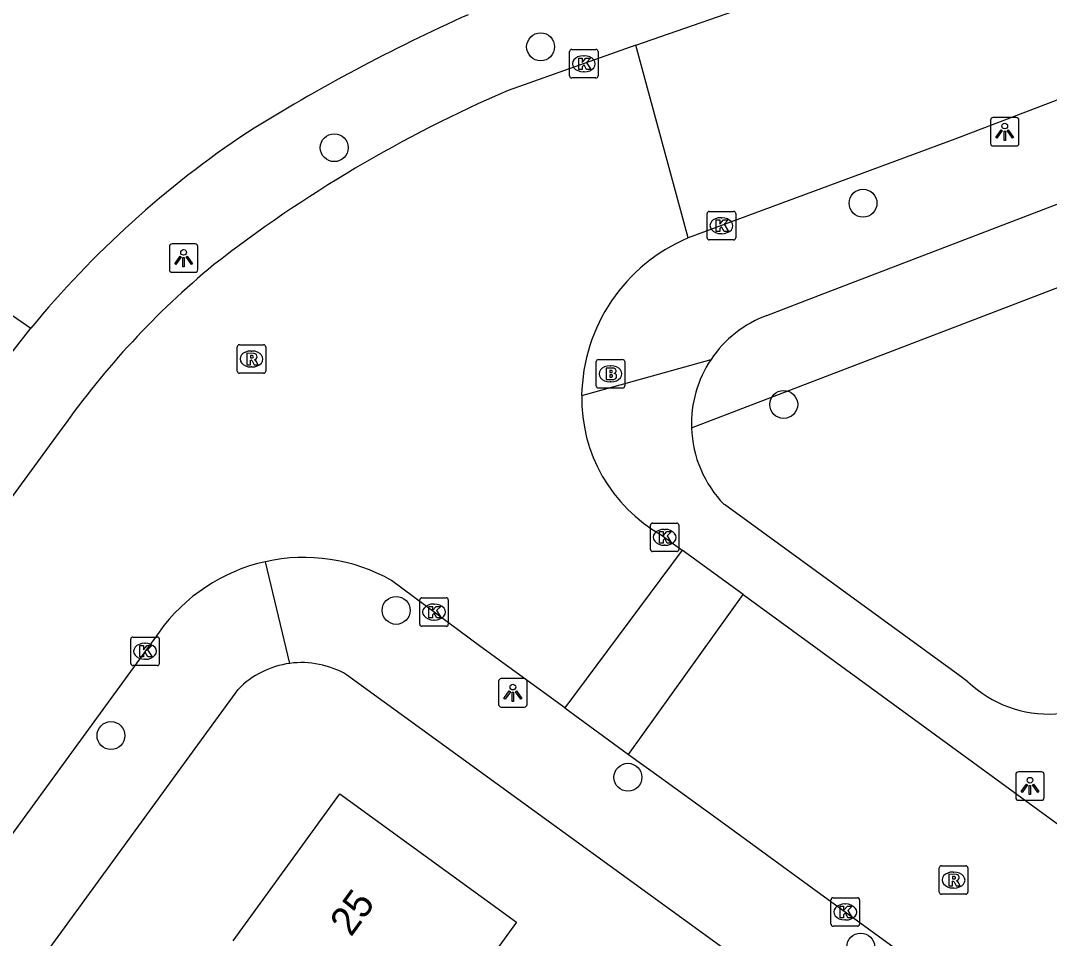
# Model space of a CAD drawing. Extents: x 159675 to 160530, y 382179 to 382901.
# Drawn here: x 160160.32 to 160196.38, y 382662.72 to 382694.9 of the extents above; entities that cross this region are included whole.
import ezdxf

# ---------------------------------------------------------------- set-up
doc = ezdxf.new("R2010")
doc.units = 0
for name, color, linetype in [('IMGEO_Boom', 7, 'Continuous'), ('IMGEO_Brandkraan', 7, 'Continuous'), ('IMGEO_Groenvoorziening', 7, 'Continuous'), ('IMGEO_Kolk', 7, 'Continuous'), ('IMGEO_Lichtpunt', 7, 'Continuous'), ('IMGEO_Pand', 7, 'Continuous'), ('IMGEO_Pand_nummerreeks', 7, 'Continuous'), ('IMGEO_Rijbaan_lokaal_open', 7, 'Continuous'), ('IMGEO_Rioolput', 7, 'Continuous'), ('IMGEO_Voetpad_halfverhard', 7, 'Continuous'), ('IMGEO_Voetpad_open', 7, 'Continuous')]:
    doc.layers.add(name, color=color, linetype=linetype)

msp = doc.modelspace()

# ---------------------------------------------------------------- linework, layer by layer
at = {"layer": 'IMGEO_Boom'}
for centre in [(160178.55, 382693.981), (160171.316, 382690.446), (160189.849, 382688.5), (160187.07, 382681.443), (160173.487, 382674.223), (160163.493, 382669.836), (160181.609, 382668.373), (160189.768, 382662.42)]:
    msp.add_circle(centre, 0.489, dxfattribs=at)
at = {"layer": 'IMGEO_Brandkraan'}
for p, q in [((160180.573, 382683.018), (160181.425, 382683.018)), ((160180.498, 382682.092), (160180.498, 382682.944)), ((160180.986, 382682.798), (160181.011, 382682.798)), ((160181.499, 382682.944), (160181.499, 382682.092)), ((160181.009, 382682.238), (160180.984, 382682.238)), ((160181.425, 382682.018), (160180.573, 382682.018))]:
    msp.add_line(p, q, dxfattribs=at)
for points in [[(160180.573, 382683.018), (160181.425, 382683.018)], [(160180.498, 382682.092), (160180.498, 382682.944)], [(160180.846, 382682.718), (160180.846, 382682.318), (160181.059, 382682.318)], [(160181.077, 382682.718), (160180.846, 382682.718)], [(160181.025, 382682.637), (160180.971, 382682.637), (160180.971, 382682.561)], [(160181.499, 382682.944), (160181.499, 382682.092)], [(160180.971, 382682.561), (160181.024, 382682.561)], [(160181.033, 382682.485), (160180.971, 382682.485), (160180.971, 382682.404)], [(160180.971, 382682.404), (160181.033, 382682.404)], [(160181.425, 382682.018), (160180.573, 382682.018)]]:
    msp.add_lwpolyline(points, dxfattribs=at)
for centre, radius, start, end in [((160180.575, 382682.942), 0.0765, 91.552, 178.448), ((160180.575, 382682.942), 0.0765, 91.552, 178.448), ((160181.423, 382682.942), 0.0765, 1.552, 88.448), ((160181.423, 382682.942), 0.0765, 1.552, 88.448), ((160181.026, 382682.599), 0.0379, 267.8285, 90.9355), ((160181.081, 382682.573), 0.145, 59.4692, 91.5367), ((160181.106, 382682.62), 0.0922, 285.5137, 58.1501), ((160181.034, 382682.444), 0.0404, 269.8759, 90.5077), ((160181.065, 382682.569), 0.251, 268.6676, 293.5347), ((160181.111, 382682.428), 0.105, 301.3115, 78.989), ((160180.575, 382682.094), 0.0765, 181.552, 268.448), ((160180.575, 382682.094), 0.0765, 181.552, 268.448), ((160181.423, 382682.094), 0.0765, 271.552, 358.448), ((160181.423, 382682.094), 0.0765, 271.552, 358.448)]:
    msp.add_arc(centre, radius, start, end, dxfattribs=at)
for centre, major_axis, ratio, start_param, end_param in [((160180.985, 382682.518), (-0.387, 0.002), 0.722429, 4.712389, 7.853982), ((160181.01, 382682.518), (-0.39, 0.002), 0.717154, 1.570796, 4.712389)]:
    msp.add_ellipse(centre, major_axis=major_axis, ratio=ratio, start_param=start_param, end_param=end_param, dxfattribs=at)
at = {"layer": 'IMGEO_Groenvoorziening'}
msp.add_lwpolyline([(160183.838, 382680.623), (160202.93, 382687.934), (160213.448, 382691.962)], dxfattribs=at)
at = {"layer": 'IMGEO_Kolk'}
for p, q in [((160179.564, 382692.963), (160179.564, 382693.815)), ((160179.639, 382693.889), (160180.491, 382693.889)), ((160180.565, 382693.815), (160180.565, 382692.963)), ((160180.052, 382693.669), (160180.077, 382693.669)), ((160180.075, 382693.109), (160180.05, 382693.109)), ((160180.491, 382692.889), (160179.639, 382692.889)), ((160184.386, 382687.285), (160184.386, 382688.137)), ((160184.461, 382688.211), (160185.313, 382688.211)), ((160185.387, 382688.137), (160185.387, 382687.285)), ((160184.874, 382687.991), (160184.899, 382687.991)), ((160184.897, 382687.431), (160184.872, 382687.431)), ((160185.313, 382687.211), (160184.461, 382687.211)), ((160182.397, 382676.359), (160182.397, 382677.211)), ((160182.472, 382677.285), (160183.324, 382677.285)), ((160183.398, 382677.211), (160183.398, 382676.359)), ((160182.885, 382677.065), (160182.91, 382677.065)), ((160182.908, 382676.505), (160182.883, 382676.505)), ((160183.324, 382676.285), (160182.472, 382676.285)), ((160174.389, 382674.666), (160175.241, 382674.666)), ((160174.314, 382673.74), (160174.314, 382674.592)), ((160174.802, 382674.446), (160174.827, 382674.446)), ((160175.315, 382674.592), (160175.315, 382673.74)), ((160175.241, 382673.666), (160174.389, 382673.666)), ((160174.825, 382673.886), (160174.8, 382673.886)), ((160164.186, 382672.364), (160164.186, 382673.216)), ((160164.261, 382673.29), (160165.113, 382673.29)), ((160165.187, 382673.216), (160165.187, 382672.364)), ((160164.674, 382673.07), (160164.699, 382673.07)), ((160164.697, 382672.51), (160164.672, 382672.51)), ((160165.113, 382672.29), (160164.261, 382672.29)), ((160188.727, 382663.225), (160188.727, 382664.077)), ((160188.802, 382664.151), (160189.654, 382664.151)), ((160189.215, 382663.931), (160189.24, 382663.931)), ((160189.728, 382664.077), (160189.728, 382663.225)), ((160189.654, 382663.151), (160188.802, 382663.151)), ((160189.238, 382663.371), (160189.213, 382663.371))]:
    msp.add_line(p, q, dxfattribs=at)
for points in [[(160179.564, 382692.963), (160179.564, 382693.815)], [(160179.639, 382693.889), (160180.491, 382693.889)], [(160180.565, 382693.815), (160180.565, 382692.963)], [(160179.885, 382693.589), (160180.008, 382693.589), (160180.008, 382693.438), (160180.138, 382693.589), (160180.302, 382693.589), (160180.156, 382693.438), (160180.309, 382693.189), (160180.157, 382693.189), (160180.072, 382693.353), (160180.008, 382693.286), (160180.008, 382693.189), (160179.885, 382693.189), (160179.885, 382693.589)], [(160180.491, 382692.889), (160179.639, 382692.889)], [(160184.386, 382687.285), (160184.386, 382688.137)], [(160184.461, 382688.211), (160185.313, 382688.211)], [(160185.387, 382688.137), (160185.387, 382687.285)], [(160184.707, 382687.911), (160184.83, 382687.911), (160184.83, 382687.76), (160184.96, 382687.911), (160185.124, 382687.911), (160184.978, 382687.76), (160185.131, 382687.511), (160184.979, 382687.511), (160184.894, 382687.675), (160184.83, 382687.608), (160184.83, 382687.511), (160184.707, 382687.511), (160184.707, 382687.911)], [(160185.313, 382687.211), (160184.461, 382687.211)], [(160182.397, 382676.359), (160182.397, 382677.211)], [(160182.472, 382677.285), (160183.324, 382677.285)], [(160183.398, 382677.211), (160183.398, 382676.359)], [(160182.718, 382676.985), (160182.841, 382676.985), (160182.841, 382676.834), (160182.971, 382676.985), (160183.135, 382676.985), (160182.989, 382676.834), (160183.142, 382676.585), (160182.99, 382676.585), (160182.905, 382676.749), (160182.841, 382676.682), (160182.841, 382676.585), (160182.718, 382676.585), (160182.718, 382676.985)], [(160183.324, 382676.285), (160182.472, 382676.285)], [(160174.389, 382674.666), (160175.241, 382674.666)], [(160174.314, 382673.74), (160174.314, 382674.592)], [(160174.635, 382674.366), (160174.758, 382674.366), (160174.758, 382674.215), (160174.888, 382674.366), (160175.052, 382674.366), (160174.906, 382674.215), (160175.059, 382673.966), (160174.907, 382673.966), (160174.822, 382674.13), (160174.758, 382674.063), (160174.758, 382673.966), (160174.635, 382673.966), (160174.635, 382674.366)], [(160175.315, 382674.592), (160175.315, 382673.74)], [(160175.241, 382673.666), (160174.389, 382673.666)], [(160164.186, 382672.364), (160164.186, 382673.216)], [(160164.261, 382673.29), (160165.113, 382673.29)], [(160165.187, 382673.216), (160165.187, 382672.364)], [(160164.507, 382672.99), (160164.63, 382672.99), (160164.63, 382672.839), (160164.76, 382672.99), (160164.924, 382672.99), (160164.778, 382672.839), (160164.931, 382672.59), (160164.779, 382672.59), (160164.694, 382672.754), (160164.63, 382672.687), (160164.63, 382672.59), (160164.507, 382672.59), (160164.507, 382672.99)], [(160165.113, 382672.29), (160164.261, 382672.29)], [(160188.727, 382663.225), (160188.727, 382664.077)], [(160188.802, 382664.151), (160189.654, 382664.151)], [(160189.048, 382663.851), (160189.171, 382663.851), (160189.171, 382663.7), (160189.301, 382663.851), (160189.465, 382663.851), (160189.319, 382663.7), (160189.472, 382663.451), (160189.32, 382663.451), (160189.235, 382663.615), (160189.171, 382663.548), (160189.171, 382663.451), (160189.048, 382663.451), (160189.048, 382663.851)], [(160189.728, 382664.077), (160189.728, 382663.225)], [(160189.654, 382663.151), (160188.802, 382663.151)]]:
    msp.add_lwpolyline(points, dxfattribs=at)
for centre, start, end in [((160179.641, 382693.813), 91.552, 178.448), ((160179.641, 382693.813), 91.552, 178.448), ((160180.489, 382693.813), 1.552, 88.448), ((160180.489, 382693.813), 1.552, 88.448), ((160179.641, 382692.965), 181.552, 268.448), ((160179.641, 382692.965), 181.552, 268.448), ((160180.489, 382692.965), 271.552, 358.448), ((160180.489, 382692.965), 271.552, 358.448), ((160184.463, 382688.135), 91.552, 178.448), ((160184.463, 382688.135), 91.552, 178.448), ((160185.311, 382688.135), 1.552, 88.448), ((160185.311, 382688.135), 1.552, 88.448), ((160184.463, 382687.287), 181.552, 268.448), ((160184.463, 382687.287), 181.552, 268.448), ((160185.311, 382687.287), 271.552, 358.448), ((160185.311, 382687.287), 271.552, 358.448), ((160182.474, 382677.209), 91.552, 178.448), ((160182.474, 382677.209), 91.552, 178.448), ((160183.322, 382677.209), 1.552, 88.448), ((160183.322, 382677.209), 1.552, 88.448), ((160182.474, 382676.361), 181.552, 268.448), ((160182.474, 382676.361), 181.552, 268.448), ((160183.322, 382676.361), 271.552, 358.448), ((160183.322, 382676.361), 271.552, 358.448), ((160174.391, 382674.59), 91.552, 178.448), ((160174.391, 382674.59), 91.552, 178.448), ((160175.239, 382674.59), 1.552, 88.448), ((160175.239, 382674.59), 1.552, 88.448), ((160174.391, 382673.742), 181.552, 268.448), ((160174.391, 382673.742), 181.552, 268.448), ((160175.239, 382673.742), 271.552, 358.448), ((160175.239, 382673.742), 271.552, 358.448), ((160164.263, 382673.214), 91.552, 178.448), ((160164.263, 382673.214), 91.552, 178.448), ((160165.111, 382673.214), 1.552, 88.448), ((160165.111, 382673.214), 1.552, 88.448), ((160164.263, 382672.366), 181.552, 268.448), ((160164.263, 382672.366), 181.552, 268.448), ((160165.111, 382672.366), 271.552, 358.448), ((160165.111, 382672.366), 271.552, 358.448), ((160188.804, 382664.075), 91.552, 178.448), ((160188.804, 382664.075), 91.552, 178.448), ((160189.652, 382664.075), 1.552, 88.448), ((160189.652, 382664.075), 1.552, 88.448), ((160188.804, 382663.227), 181.552, 268.448), ((160188.804, 382663.227), 181.552, 268.448), ((160189.652, 382663.227), 271.552, 358.448), ((160189.652, 382663.227), 271.552, 358.448)]:
    msp.add_arc(centre, 0.0765, start, end, dxfattribs=at)
for centre, major_axis, ratio, start_param, end_param in [((160180.051, 382693.389), (-0.387, 0.002), 0.722429, 4.712389, 7.853982), ((160180.076, 382693.389), (-0.39, 0.002), 0.717154, 1.570796, 4.712389), ((160184.873, 382687.711), (-0.387, 0.002), 0.722429, 4.712389, 7.853982), ((160184.898, 382687.711), (-0.39, 0.002), 0.717154, 1.570796, 4.712389), ((160182.884, 382676.785), (-0.387, 0.002), 0.722429, 4.712389, 7.853982), ((160182.909, 382676.785), (-0.39, 0.002), 0.717154, 1.570796, 4.712389), ((160174.801, 382674.166), (-0.387, 0.002), 0.722429, 4.712389, 7.853982), ((160174.826, 382674.166), (-0.39, 0.002), 0.717154, 1.570796, 4.712389), ((160164.673, 382672.79), (-0.387, 0.002), 0.722429, 4.712389, 7.853982), ((160164.698, 382672.79), (-0.39, 0.002), 0.717154, 1.570796, 4.712389), ((160189.214, 382663.651), (-0.387, 0.002), 0.722429, 4.712389, 7.853982), ((160189.239, 382663.651), (-0.39, 0.002), 0.717154, 1.570796, 4.712389)]:
    msp.add_ellipse(centre, major_axis=major_axis, ratio=ratio, start_param=start_param, end_param=end_param, dxfattribs=at)
at = {"layer": 'IMGEO_Lichtpunt'}
for p, q in [((160194.318, 382691.407), (160194.318, 382690.6)), ((160194.318, 382691.407), (160194.318, 382690.6)), ((160195.22, 382691.502), (160194.412, 382691.502)), ((160195.22, 382691.502), (160194.412, 382691.502)), ((160195.314, 382690.6), (160195.314, 382691.407)), ((160195.314, 382690.6), (160195.314, 382691.407)), ((160194.412, 382690.506), (160195.22, 382690.506)), ((160194.412, 382690.506), (160195.22, 382690.506)), ((160165.539, 382686.978), (160165.539, 382686.171)), ((160165.539, 382686.978), (160165.539, 382686.171)), ((160166.441, 382687.073), (160165.633, 382687.073)), ((160166.441, 382687.073), (160165.633, 382687.073)), ((160166.535, 382686.171), (160166.535, 382686.978)), ((160166.535, 382686.171), (160166.535, 382686.978)), ((160165.633, 382686.077), (160166.441, 382686.077)), ((160165.633, 382686.077), (160166.441, 382686.077)), ((160177.981, 382671.832), (160177.173, 382671.832)), ((160177.981, 382671.832), (160177.173, 382671.832)), ((160177.079, 382671.737), (160177.079, 382670.93)), ((160177.079, 382671.737), (160177.079, 382670.93)), ((160178.075, 382670.93), (160178.075, 382671.737)), ((160178.075, 382670.93), (160178.075, 382671.737)), ((160177.173, 382670.836), (160177.981, 382670.836)), ((160177.173, 382670.836), (160177.981, 382670.836)), ((160196.103, 382668.565), (160195.295, 382668.565)), ((160196.103, 382668.565), (160195.295, 382668.565)), ((160195.201, 382668.47), (160195.201, 382667.663)), ((160195.201, 382668.47), (160195.201, 382667.663)), ((160196.197, 382667.663), (160196.197, 382668.47)), ((160196.197, 382667.663), (160196.197, 382668.47)), ((160195.295, 382667.569), (160196.103, 382667.569)), ((160195.295, 382667.569), (160196.103, 382667.569))]:
    msp.add_line(p, q, dxfattribs=at)
for points in [[(160194.692, 382691.071), (160194.731, 382691.043), (160194.543, 382690.781), (160194.505, 382690.808), (160194.692, 382691.071)], [(160194.794, 382691.023), (160194.841, 382691.023), (160194.841, 382690.701), (160194.794, 382690.701), (160194.794, 382691.023)], [(160194.904, 382691.043), (160194.942, 382691.07), (160195.129, 382690.808), (160195.09, 382690.78), (160194.904, 382691.043)], [(160165.913, 382686.642), (160165.952, 382686.614), (160165.764, 382686.352), (160165.726, 382686.379), (160165.913, 382686.642)], [(160166.015, 382686.594), (160166.062, 382686.594), (160166.062, 382686.272), (160166.015, 382686.272), (160166.015, 382686.594)], [(160166.125, 382686.614), (160166.163, 382686.641), (160166.35, 382686.379), (160166.311, 382686.351), (160166.125, 382686.614)], [(160177.453, 382671.401), (160177.492, 382671.373), (160177.304, 382671.111), (160177.266, 382671.138), (160177.453, 382671.401)], [(160177.555, 382671.353), (160177.602, 382671.353), (160177.602, 382671.031), (160177.555, 382671.031), (160177.555, 382671.353)], [(160177.665, 382671.373), (160177.703, 382671.4), (160177.89, 382671.138), (160177.851, 382671.11), (160177.665, 382671.373)], [(160195.575, 382668.134), (160195.614, 382668.106), (160195.426, 382667.844), (160195.388, 382667.871), (160195.575, 382668.134)], [(160195.677, 382668.086), (160195.724, 382668.086), (160195.724, 382667.764), (160195.677, 382667.764), (160195.677, 382668.086)], [(160195.787, 382668.106), (160195.825, 382668.133), (160196.012, 382667.871), (160195.973, 382667.843), (160195.787, 382668.106)]]:
    msp.add_lwpolyline(points, dxfattribs=at)
for centre in [(160194.817, 382691.205), (160166.038, 382686.776), (160177.578, 382671.535), (160195.7, 382668.268)]:
    msp.add_circle(centre, 0.0994, dxfattribs=at)
for centre, start, end in [((160194.412, 382691.407), 90, 180), ((160194.412, 382691.407), 90, 180), ((160195.22, 382691.407), 0, 90), ((160195.22, 382691.407), 0, 90), ((160194.412, 382690.6), 180, 270), ((160194.412, 382690.6), 180, 270), ((160195.22, 382690.6), 270, 0), ((160195.22, 382690.6), 270, 360), ((160165.633, 382686.978), 90, 180), ((160165.633, 382686.978), 90, 180), ((160166.441, 382686.978), 0, 90), ((160166.441, 382686.978), 0, 90), ((160165.633, 382686.171), 180, 270), ((160165.633, 382686.171), 180, 270), ((160166.441, 382686.171), 270, 0), ((160166.441, 382686.171), 270, 360), ((160177.173, 382671.737), 90, 180), ((160177.173, 382671.737), 90, 180), ((160177.981, 382671.737), 0, 90), ((160177.981, 382671.737), 0, 90), ((160177.173, 382670.93), 180, 270), ((160177.173, 382670.93), 180, 270), ((160177.981, 382670.93), 270, 0), ((160177.981, 382670.93), 270, 360), ((160195.295, 382668.47), 90, 180), ((160195.295, 382668.47), 90, 180), ((160196.103, 382668.47), 0, 90), ((160196.103, 382668.47), 0, 90), ((160195.295, 382667.663), 180, 270), ((160195.295, 382667.663), 180, 270), ((160196.103, 382667.663), 270, 0), ((160196.103, 382667.663), 270, 360)]:
    msp.add_arc(centre, 0.0946, start, end, dxfattribs=at)
at = {"layer": 'IMGEO_Pand'}
msp.add_lwpolyline([(160167.772, 382662.643), (160171.514, 382667.791), (160177.706, 382663.29), (160173.964, 382658.142)], dxfattribs=at)
at = {"layer": 'IMGEO_Rijbaan_lokaal_open'}
for points in [[(160265.882, 382729.271), (160254.768, 382722.388), (160236.066, 382710.925), (160220.039, 382702.396), (160212.586, 382698.728), (160201.751, 382694.067), (160193.069, 382690.742), (160183.725, 382687.281)], [(160181.888, 382694.035), (160188.447, 382696.325)], [(160181.888, 382694.035), (160177.41, 382692.449)], [(160183.725, 382687.281), (160181.888, 382694.035)], [(160161.775, 382680.602), (160146.792, 382660.104), (160134.723, 382643.445), (160133.916, 382642.352)], [(160182.774, 382676.874), (160183.513, 382676.335)], [(160183.513, 382676.335), (160179.396, 382670.806)], [(160185.646, 382674.779), (160183.513, 382676.335)], [(160179.396, 382670.806), (160176.449, 382672.951), (160173.328, 382675.273)], [(160181.634, 382669.177), (160185.646, 382674.779)], [(160185.646, 382674.779), (160197.707, 382665.98), (160216.435, 382652.317)], [(160165.176, 382673.46), (160154.667, 382659.043), (160140.62, 382639.505), (160139.698, 382638.176)], [(160179.396, 382670.806), (160181.634, 382669.177)], [(160181.634, 382669.177), (160182.782, 382668.342), (160184.861, 382666.829), (160188.065, 382664.498), (160193.64, 382660.441), (160226.048, 382636.856)]]:
    msp.add_lwpolyline(points, dxfattribs=at)
for centre, radius, start, end in [((160195.887, 382649.501), 46.754, 113.2779, 128.0189), ((160186.08, 382681.663), 6.092, 112.7421, 179.1248), ((160185.8, 382663.655), 29.4, 129.5222, 144.8013), ((160185.497, 382681.663), 5.509, 179.0299, 240.3764), ((160170.257, 382669.845), 6.235, 102.5283, 144.5676), ((160170.259, 382669.848), 6.233, 60.502, 102.553)]:
    msp.add_arc(centre, radius, start, end, dxfattribs=at)
at = {"layer": 'IMGEO_Rioolput'}
for p, q in [((160167.916, 382682.611), (160167.916, 382683.463)), ((160167.991, 382683.537), (160168.843, 382683.537)), ((160168.404, 382683.317), (160168.429, 382683.317)), ((160168.917, 382683.463), (160168.917, 382682.611)), ((160168.427, 382682.757), (160168.402, 382682.757)), ((160168.843, 382682.537), (160167.991, 382682.537)), ((160192.522, 382664.345), (160192.522, 382665.197)), ((160192.597, 382665.271), (160193.449, 382665.271)), ((160193.01, 382665.051), (160193.035, 382665.051)), ((160193.523, 382665.197), (160193.523, 382664.345)), ((160193.449, 382664.271), (160192.597, 382664.271)), ((160193.033, 382664.491), (160193.008, 382664.491))]:
    msp.add_line(p, q, dxfattribs=at)
for points in [[(160167.916, 382682.611), (160167.916, 382683.463)], [(160167.991, 382683.537), (160168.843, 382683.537)], [(160168.917, 382683.463), (160168.917, 382682.611)], [(160168.505, 382683.235), (160168.253, 382683.237), (160168.253, 382682.837)], [(160168.253, 382682.837), (160168.377, 382682.837), (160168.377, 382682.999), (160168.388, 382682.999)], [(160168.431, 382683.156), (160168.377, 382683.156), (160168.377, 382683.075)], [(160168.377, 382683.075), (160168.429, 382683.075)], [(160168.435, 382682.97), (160168.506, 382682.837), (160168.646, 382682.837), (160168.581, 382682.963)], [(160168.843, 382682.537), (160167.991, 382682.537)], [(160192.522, 382664.345), (160192.522, 382665.197)], [(160192.597, 382665.271), (160193.449, 382665.271)], [(160193.111, 382664.969), (160192.859, 382664.971), (160192.859, 382664.571)], [(160193.523, 382665.197), (160193.523, 382664.345)], [(160192.859, 382664.571), (160192.983, 382664.571), (160192.983, 382664.733), (160192.994, 382664.733)], [(160193.037, 382664.89), (160192.983, 382664.89), (160192.983, 382664.809)], [(160192.983, 382664.809), (160193.035, 382664.809)], [(160193.041, 382664.704), (160193.112, 382664.571), (160193.252, 382664.571), (160193.187, 382664.697)], [(160193.449, 382664.271), (160192.597, 382664.271)]]:
    msp.add_lwpolyline(points, dxfattribs=at)
for centre, radius, start, end in [((160167.993, 382683.461), 0.0765, 91.552, 178.448), ((160167.993, 382683.461), 0.0765, 91.552, 178.448), ((160168.841, 382683.461), 0.0765, 1.552, 88.448), ((160168.841, 382683.461), 0.0765, 1.552, 88.448), ((160168.387, 382682.946), 0.0533, 26.0293, 88.6989), ((160168.413, 382683.264), 0.19, 274.7715, 282.9687), ((160168.437, 382683.06), 0.0964, 77.0061, 93.1865), ((160168.451, 382683.117), 0.0378, 276.6634, 79.6772), ((160168.504, 382683.125), 0.109, 350.3612, 89.416), ((160168.502, 382683.125), 0.112, 277.5842, 350.9817), ((160168.486, 382682.91), 0.108, 29.5134, 73.7905), ((160167.993, 382682.613), 0.0765, 181.552, 268.448), ((160167.993, 382682.613), 0.0765, 181.552, 268.448), ((160168.841, 382682.613), 0.0765, 271.552, 358.448), ((160168.841, 382682.613), 0.0765, 271.552, 358.448), ((160192.599, 382665.195), 0.0765, 91.552, 178.448), ((160192.599, 382665.195), 0.0765, 91.552, 178.448), ((160193.11, 382664.859), 0.109, 350.3612, 89.416), ((160193.447, 382665.195), 0.0765, 1.552, 88.448), ((160193.447, 382665.195), 0.0765, 1.552, 88.448), ((160192.993, 382664.68), 0.0533, 26.0293, 88.6989), ((160193.019, 382664.998), 0.19, 274.7715, 282.9687), ((160193.043, 382664.794), 0.0964, 77.0061, 93.1865), ((160193.057, 382664.851), 0.0378, 276.6634, 79.6772), ((160193.108, 382664.859), 0.112, 277.5842, 350.9817), ((160193.092, 382664.644), 0.108, 29.5134, 73.7905), ((160192.599, 382664.347), 0.0765, 181.552, 268.448), ((160192.599, 382664.347), 0.0765, 181.552, 268.448), ((160193.447, 382664.347), 0.0765, 271.552, 358.448), ((160193.447, 382664.347), 0.0765, 271.552, 358.448)]:
    msp.add_arc(centre, radius, start, end, dxfattribs=at)
for centre, major_axis, ratio, start_param, end_param in [((160168.403, 382683.037), (-0.387, 0.002), 0.722429, 4.712389, 7.853982), ((160168.428, 382683.037), (-0.39, 0.002), 0.717154, 1.570796, 4.712389), ((160193.009, 382664.771), (-0.387, 0.002), 0.722429, 4.712389, 7.853982), ((160193.034, 382664.771), (-0.39, 0.002), 0.717154, 1.570796, 4.712389)]:
    msp.add_ellipse(centre, major_axis=major_axis, ratio=ratio, start_param=start_param, end_param=end_param, dxfattribs=at)
at = {"layer": 'IMGEO_Voetpad_halfverhard'}
msp.add_lwpolyline([(160195.172, 382715.185), (160176.655, 382705.893), (160155.741, 382695.129), (160152.195, 382692.551), (160152.254, 382691.404), (160152.332, 382689.883), (160160.682, 382684.114)], dxfattribs=at)
at = {"layer": 'IMGEO_Voetpad_open'}
for points in [[(160186.481, 382684.566), (160188.471, 382685.328), (160200.956, 382690.11), (160211.247, 382694.051)], [(160158.819, 382681.732), (160160.682, 382684.114)], [(160179.989, 382681.756), (160184.522, 382683.022)], [(160193.528, 382671.722), (160193.242, 382671.93), (160184.989, 382677.933)], [(160169.761, 382672.365), (160168.904, 382675.932)], [(160191.584, 382657.525), (160191.549, 382657.592), (160171.75, 382671.968)], [(160141.366, 382634.961), (160167.947, 382671.456)]]:
    msp.add_lwpolyline(points, dxfattribs=at)
for centre, radius, start, end in [((160202.164, 382636.775), 63.929, 114.15169, 122.01328), ((160187.625, 382661.961), 34.88, 123.6949, 140.5724), ((160187.895, 382680.757), 4.063, 110.3666, 146.1207), ((160187.894, 382680.764), 4.058, 146.1872, 181.9851), ((160187.882, 382680.762), 4.047, 181.9709, 224.3594), ((160170.176, 382669.272), 3.121, 97.6459, 135.5853), ((160170.176, 382669.263), 3.13, 59.8056, 97.6189), ((160196.352, 382674.673), 4.084, 226.2608, 320.6462)]:
    msp.add_arc(centre, radius, start, end, dxfattribs=at)

# ---------------------------------------------------------------- texts
at = {"layer": 'IMGEO_Pand_nummerreeks'}
msp.add_text('25', height=1, rotation=53.9858, dxfattribs=at).set_placement((160171.904, 382662.749))

doc.saveas('drawing.dxf')
